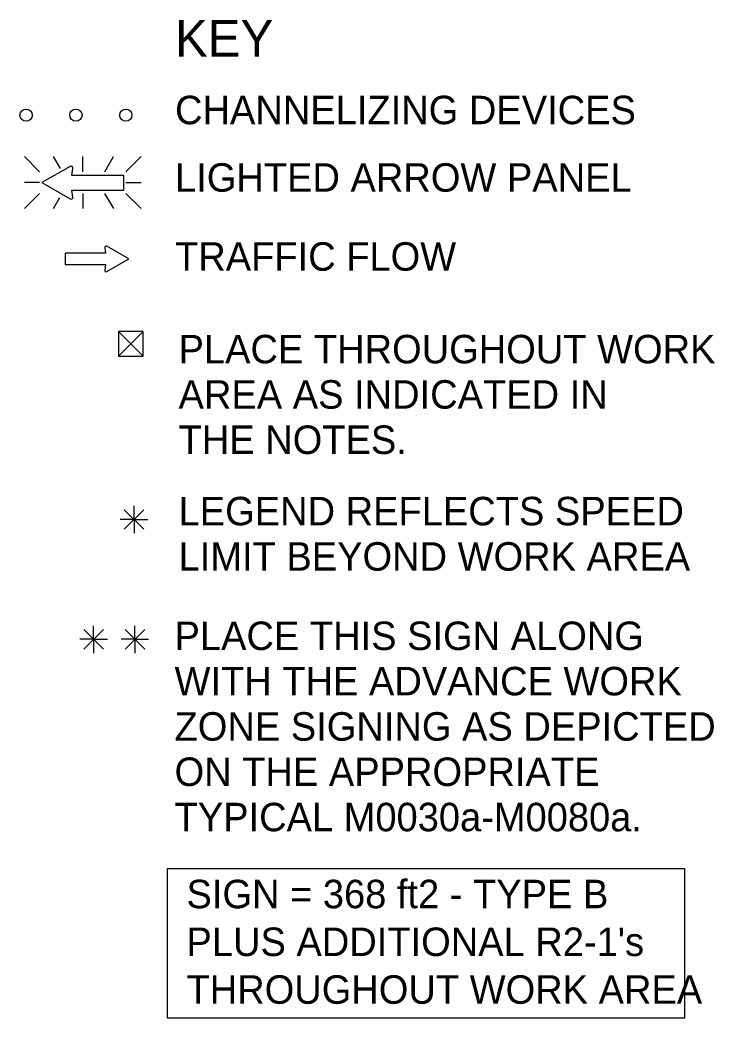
# Model space of a CAD drawing. Extents: x 16726 to 18479, y 5932 to 7023.
# Drawn here: x 17181.6 to 17408.9, y 6586.4 to 6912.4 of the extents above; entities that cross this region are included whole.
import ezdxf

# ---------------------------------------------------------------- set-up
doc = ezdxf.new("R2010")
doc.units = 0
for name, color, linetype in [('MT_SCRATCH_LEVEL_E', 7, 'Continuous'), ('TRAFFIC_SIGNS_PR', 7, 'Continuous'), ('TYPICAL_TEXT_DIMEN_EX', 7, 'Continuous'), ('TYPICAL_TEXT_DIMEN_PR', 7, 'Continuous')]:
    doc.layers.add(name, color=color, linetype=linetype)

msp = doc.modelspace()

# ---------------------------------------------------------------- linework, layer by layer
at = {"layer": 'MT_SCRATCH_LEVEL_E'}
for p, q in [((17209.66, 6836.18), (17196.4, 6836.18)), ((17196.4, 6836.18), (17196.4, 6832.44)), ((17209.35, 6837.96), (17209.66, 6836.18)), ((17217.27, 6834.33), (17210.03, 6838.44)), ((17210.03, 6830.19), (17217.27, 6834.33)), ((17196.4, 6832.44), (17209.66, 6832.44)), ((17209.66, 6832.44), (17209.35, 6830.66))]:
    msp.add_line(p, q, dxfattribs=at)
for centre, start, end in [((17209.81, 6838.04), 60.4248, 189.9638), ((17209.81, 6830.59), 170.0362, 299.7731)]:
    msp.add_arc(centre, 0.463, start, end, dxfattribs=at)
at = {"layer": 'TRAFFIC_SIGNS_PR'}
for p, q in [((17183.08, 6867.71), (17188.02, 6862.78)), ((17194.85, 6863.89), (17192.64, 6867.72)), ((17202.17, 6862.78), (17202.17, 6867.72)), ((17209.4, 6862.78), (17212.25, 6867.72)), ((17216.31, 6862.78), (17221.25, 6867.72)), ((17188.02, 6859.23), (17183.08, 6859.23)), ((17216.31, 6859.23), (17221.25, 6859.23)), ((17183.08, 6850.74), (17188.02, 6855.67)), ((17192.59, 6850.74), (17194.71, 6854.4)), ((17202.17, 6855.67), (17202.17, 6850.74)), ((17212.29, 6850.74), (17209.44, 6855.67)), ((17216.31, 6855.67), (17221.25, 6850.73))]:
    msp.add_line(p, q, dxfattribs=at)
for points in [[(17198.09, 6864.5), (17188.8, 6859.23), (17198.1, 6853.9)], [(17198.97, 6854.53), (17198.57, 6856.8), (17215.58, 6856.8), (17215.58, 6861.6), (17198.57, 6861.6), (17198.97, 6863.88)]]:
    msp.add_lwpolyline(points, dxfattribs=at)
for centre in [(17183.65, 6881.26), (17199.95, 6881.26), (17216.25, 6881.26)]:
    msp.add_circle(centre, 2, dxfattribs=at)
for centre, radius, start, end in [((17198.38, 6863.98), 0.598, 350.7308, 118.8916), ((17198.38, 6854.43), 0.597, 241.4833, 9.9593)]:
    msp.add_arc(centre, radius, start, end, dxfattribs=at)
at = {"layer": 'TYPICAL_TEXT_DIMEN_EX'}
msp.add_lwpolyline([(17229.85, 6635.19), (17398.86, 6635.19), (17398.86, 6586.36), (17229.85, 6586.36)], close=True, dxfattribs=at)
at = {"layer": 'TYPICAL_TEXT_DIMEN_PR'}
for p, q in [((17213.9, 6802.55), (17221.9, 6810.55)), ((17213.91, 6810.55), (17221.9, 6802.55)), ((17215.76, 6752.37), (17222.14, 6746)), ((17222.14, 6752.37), (17215.76, 6746)), ((17218.95, 6749.19), (17218.95, 6753.64)), ((17218.95, 6749.19), (17214.42, 6749.19)), ((17218.95, 6749.19), (17222.14, 6749.19)), ((17218.95, 6749.19), (17223.43, 6749.19)), ((17218.95, 6749.19), (17218.95, 6744.69)), ((17202.54, 6713.24), (17208.92, 6706.87)), ((17208.92, 6713.24), (17202.54, 6706.87)), ((17205.73, 6710.06), (17205.73, 6714.51)), ((17216.05, 6713.24), (17222.42, 6706.87)), ((17222.42, 6713.24), (17216.05, 6706.87)), ((17219.23, 6710.06), (17219.23, 6714.51)), ((17205.73, 6710.06), (17201.2, 6710.06)), ((17205.73, 6710.06), (17208.92, 6710.06)), ((17205.73, 6710.06), (17210.21, 6710.06)), ((17205.73, 6710.06), (17205.73, 6705.56)), ((17219.23, 6710.06), (17214.7, 6710.06)), ((17219.23, 6710.06), (17222.42, 6710.06)), ((17219.23, 6710.06), (17223.71, 6710.06)), ((17219.23, 6710.06), (17219.23, 6705.56))]:
    msp.add_line(p, q, dxfattribs=at)
msp.add_lwpolyline([(17213.91, 6810.55), (17213.9, 6802.55), (17221.9, 6802.55), (17221.9, 6810.55)], close=True, dxfattribs=at)
msp.add_open_spline([(17311.9, 6749.77), (17311.92, 6749.77), (17311.93, 6749.77), (17311.93, 6749.77)], degree=2, dxfattribs=at)

# ---------------------------------------------------------------- texts
at = {"layer": 'TYPICAL_TEXT_DIMEN_EX'}
for s, height, p in [('KEY', 12, (17232.34, 6900.36)), ('CHANNELIZING DEVICES', 9.3, (17232.34, 6878.31)), ('LIGHTED ARROW PANEL', 9.3, (17232.34, 6856.26)), ('TRAFFIC FLOW', 9.3, (17232.34, 6830.46)), ('PLACE THROUGHOUT WORK', 9.3, (17233.49, 6800.2)), ('AREA AS INDICATED IN', 9.3, (17233.49, 6785.4)), ('THE NOTES.', 9.3, (17233.49, 6770.6)), ('LEGEND REFLECTS SPEED', 9.3, (17233.5, 6747.29)), ('LIMIT BEYOND WORK AREA', 9.3, (17233.5, 6732.49)), ('PLACE THIS SIGN ALONG', 9.3, (17232.18, 6706.56)), ('WITH THE ADVANCE WORK', 9.3, (17232.18, 6691.76)), ('ZONE SIGNING AS DEPICTED', 9.3, (17232.18, 6676.96)), ('ON THE APPROPRIATE', 9.3, (17232.18, 6662.16)), ('TYPICAL M0030a-M0080a.', 9.3, (17232.18, 6647.36)), ('SIGN = 368 ft2 - TYPE B', 9.3, (17236.08, 6622.22)), ("PLUS ADDITIONAL R2-1's", 9.3, (17236.08, 6606.62)), ('THROUGHOUT WORK AREA', 9.3, (17236.08, 6591.02))]:
    msp.add_text(s, height=height, dxfattribs=at).set_placement(p)

doc.saveas('drawing.dxf')
